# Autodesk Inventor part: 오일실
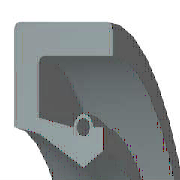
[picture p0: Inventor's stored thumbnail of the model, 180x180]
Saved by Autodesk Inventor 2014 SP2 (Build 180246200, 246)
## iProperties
IsCustomPart: 0
Created: 2016-05
Part Number: 오일실
Material: 고무
Description: 오일-실
Document SubType Name: Modeling
Standard: KS B 2804
Designer: mduedu
Standards Organization: KS
Language: ko-KR
Size Designation: S - 17 30 8
Categories: <MemberInstance><Categories><Category DisplayName="샤프트 부품" InternalName="7f7aeb1f-a693-4053-b835-cee3144e0d98" Mnemonic="SHFT"><Category DisplayName="실링" Intern
Density: 0.93 g/cm^3
Appearance: 고무 - 검은색 - 버전 1.1
Author: mduedu
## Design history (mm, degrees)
revolve "본체" stored, may be unused: angle "d17" = 90 deg
revolve "스프링1" stored, may be unused: angle "d18" = 90 deg
body "Solid1"
sketch "스케치1"
  geometry: L1 (0, 15)-(8, 15); L2 (8, 15)-(8, 13.75); L3 (8, 13.75)-(1.75, 13.75); L4 (0, 15)-(0, 10.6); L5 (0, 10.6)-(1.75, 10.25); L6 (1.75, 10.25)-(4.9, 8.5); L7 (4.9, 8.5)-(0, 8.5); L8 (6.3, 9.375)-(6.3, 10.6); L9 (0, 0)-(9.586, 0) reference; L10 (4.9, 8.5)-(6.3, 9.375); L11 (0, 18)-(0, -3) reference; L12 (-1.917, 0)-(11.503, 0) reference; L13 (4.2, 10.6)-(1.75, 11.09); L14 (1.75, 11.09)-(1.75, 13.75); L15 (6.3, 10.6)-(5.6, 10.6); C1 r 0.455 at (4.9, 10.6); A1 r 0.7 centre (4.9, 10.6) between (5.6, 10.6) and (4.2, 10.6)
  constraints: 26 end point, 5 horizontal alignment, 4 perpendicular, 2 centre point, 2 collinear, 2 horizontal, 2 parallel, 2 point on circle, 2 point on line, 2 vertical alignment, 1 coincident
  dimensions: "d0" = 30 diameter of L1 L9 (= SD2); "d1" = 18.75 diameter of L8.start L9 (= ABDM); "d2" = 1.25 distance of L1.end L2.end (computed from SD); "d3" = 0.91 diameter of C1 (= SPDI); "d4" = 1.4 diameter of A1 (= SPDA); "d5" = 17 diameter of L6.end L9 (= NND); "d6" = 20.5 diameter of L5.end L9 (= TKDM); "d7" = 21.2 diameter of L4.end L9 (= HLDM); "d8" = 4.9 distance from line of C1.centre L4 (= SPDST); "d9" = 6.3 distance between parallel lines of L8 L4 (= SDI); "d10" = 8 distance between parallel lines of L2 L4 (= SWDT); "d12" = 1.75 distance between parallel lines of L14 L4 (= SD)
fillet "모깎기1" dims "d11" = 0.3 (= RR)
other parameters: "SD2" = 30 [user parameter; used in 1 equation term], "SWDT" = 8 [user parameter; used in 1 equation term], "RR" = 0.3 [user parameter; used in 1 equation term], "SD" = 1.75 [user parameter; used in 2 equation terms], "NND" = 17 [user parameter; used in 1 equation term], "SPDA" = 1.4 [user parameter; used in 1 equation term], "SPDI" = 0.91 [user parameter; used in 1 equation term], "TKDM" = 20.5 [user parameter; used in 1 equation term], "HLDM" = 21.2 [user parameter; used in 1 equation term], "ABDM" = 18.75 [user parameter; used in 1 equation term], "SDI" = 6.3 [user parameter; used in 1 equation term], "SPDST" = 4.9 [user parameter; used in 1 equation term], "d13" = 0, "d14" = 0, "d15" = 0, "LAB" = 0.35 [user parameter]
